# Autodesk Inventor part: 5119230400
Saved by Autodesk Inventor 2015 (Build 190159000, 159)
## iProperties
Created: 2020-07
Part Number: 5119230400
Checked By: TraceParts S.A.
Material: Generic
Catalog Web Link: www.traceparts.com
Document SubType Name: Modeling
Designer: TraceParts
Density: 1 g/cm^3
Appearance: Default
Company: TraceParts S.A.
Author: TraceParts
REFERENCE: 5119230400
DESIGN: HIT-800 P 0,55KW (230/400V 50HZ) - 5119230400
SUPPLIER: Soler & Palau
TraceParts.PartNumber: 10-20122018-119595
TraceParts.PartTitle: HIB-P/HIT-P
TraceParts.InstanceId: 10-20122018-1195955V8KEO342IUGFIMHLUZ2IWEW4
TraceParts.PartStatus: Published
TraceParts.PartVersion: 1.0.2
TRACEPARTS: TRACEPARTS
TraceParts.PartLanguage: en
TraceParts.ClassPath: SOLER_PALAU:10-20122018-119595
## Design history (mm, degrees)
feature "5119230400"
body "Solid1"
